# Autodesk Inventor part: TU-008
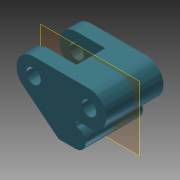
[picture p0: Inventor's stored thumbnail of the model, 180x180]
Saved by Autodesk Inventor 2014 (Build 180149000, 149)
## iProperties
Shininess: 64.0
Angle Display Precision: 2
Document Length Units: 11269
Document Angle Units: 11279
Document Time Units: 11290
Document Mass Units: 11286
Document Length Units Precision: 3
Document Angle Units Precision: 2
Created: 2002-07
Part Number: TU-008
Document SubType Name: Modeling
Designer: PN
Density: 1 g/cm^3
Description: Hinge
Mass: 25.6282 g
Surface Area: 85.6046 cm^2
Volume: 25.6282 cm^3
Material: Generic
Appearance: Smooth - Dark Cadet Blue
Density: 0.0
Volumn: 0.0
Area: 0.0
PropertySet Name: Model Information
Control State: 0
Master: False
Checked Out: False
LENGTH: 1.000 in
Author: PN
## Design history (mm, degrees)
sketch "Sketch1"
  geometry: L1 (31, 0)-(0, 0); L2 (14, -32.84)-(-5.582, -17.187); L3 (23.513, -32.84)-(14, -32.84); L4 (31, -19)-(25, -19); C1 r 4 at (0, -9.5); C2 r 4 at (31, -9.5); A1 r 9.5 centre (0, -9.5) between (0, 0) and (-5.582, -17.187); A2 r 5.5 centre (23.513, -27.34) between (23.513, -32.84) and (24.681, -21.966); A3 r 1.5 centre (25, -20.5) between (25, -19) and (24.681, -21.966); A4 r 9.5 centre (31, -9.5) between (31, -19) and (31, 0); 1 further point
  constraints: 8 end point, 8 point on circle, 7 tangent, 6 centre point, 2 coincident with centre, 2 parallel, 1 coincident, 1 equal radius, 1 horizontal
  dimensions: "d0" = 9.5 radius of A1; "d1" = 8 diameter of C1; "d2" = 31 distance of A4.centre A1.centre; "d3" = 1.5 radius of A3; "d4" = 5.5 radius of A2; "d6" = 9.51297 distance of L3.start L2.start; "d7" = 38.6376 deg angle of L3 L2; "d9" = 32.84023 distance between parallel lines of L3 L1; "d10" = 16.91036 distance from line of point (0, 0) L2
extrude "Extrusion1" new body sketch "Sketch1" stored distance "d11" = 32; taper "d12" = 0 deg
sketch "Sketch2"
  geometry: L1 (0, -32)-(0, 0) reference; L2 (-23.5, -32)-(-23.5, 0) reference; L3 (-23.5, -24)-(2, -24); L4 (2, -24)-(2, -8); L5 (2, -8)-(-23.5, -8); L6 (-23.5, -8)-(-23.5, -24); 1 further point
  constraints: 8 end point, 2 midpoint, 2 parallel, 1 horizontal, 1 perpendicular
  dimensions: "d13" = 2 distance between parallel lines of L4 L1; "d14" = 16 distance of L5.end L3.start
extrude "Extrusion2" cut sketch "Sketch2" stored distance "d15" = 32; taper "d16" = 0 deg
hole "Hole1" diameter "d19" = 8; stored, may be unused: countersink angle "d23" = 90 deg, drill point angle "d25" = 118 deg; dims "d17" = 10, "d18" = 10, "d20" = 6, "d21" = 4, "d22" = 2, "d24" = 8
hole "Hole2" diameter "d28" = 8; stored, may be unused: countersink angle "d32" = 90 deg, drill point angle "d34" = 118 deg; dims "d26" = 10, "d27" = 10, "d29" = 6, "d30" = 4, "d31" = 2, "d33" = 8
body "Solid1"
other parameters: "LENGTH" = 25.4 [user parameter]
